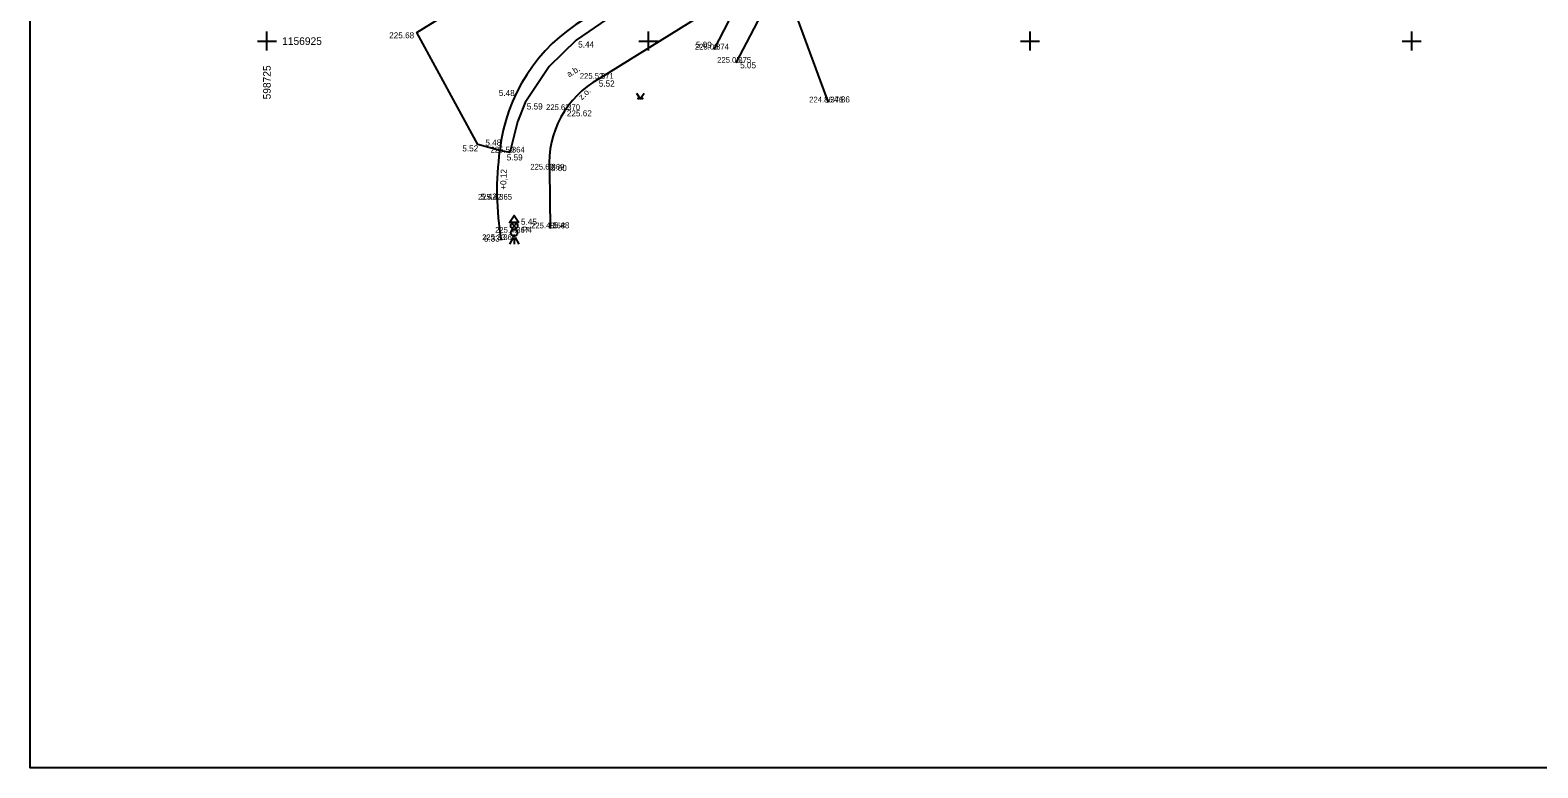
# Model space of a CAD drawing. Extents: x -598741 to -598592, y -1156973 to -1156763.
# Drawn here: x -598740.5 to -598641.7, y -1156972.6 to -1156924.3 of the extents above; entities that cross this region are included whole.
import ezdxf

# ---------------------------------------------------------------- set-up
doc = ezdxf.new("R2010")
doc.units = 0
for name, color, linetype in [('Vrstva 1', 7, 'Continuous'), ('Vrstva 10', 7, 'Continuous'), ('Vrstva 14', 7, 'Continuous'), ('Vrstva 2', 7, 'Continuous'), ('Vrstva 3', 7, 'Continuous'), ('Vrstva 44', 7, 'Continuous'), ('Vrstva 49', 7, 'Continuous'), ('Vrstva 50', 7, 'Continuous'), ('Vrstva 52', 7, 'Continuous'), ('Vrstva 58', 7, 'Continuous'), ('Vrstva 61', 7, 'Continuous'), ('Vrstva 62', 7, 'Continuous'), ('Vrstva 63', 7, 'Continuous'), ('Vrstva 7', 7, 'Continuous')]:
    doc.layers.add(name, color=color, linetype=linetype)

msp = doc.modelspace()

# ---------------------------------------------------------------- linework, layer by layer
at = {"layer": 'Vrstva 1'}
for p, q in [((-598695.71, -1156925.55), (-598695.71, -1156925.55)), ((-598694.25, -1156926.42), (-598694.25, -1156926.42)), ((-598703.25, -1156927.47), (-598703.25, -1156927.47)), ((-598705.46, -1156929.52), (-598705.46, -1156929.52)), ((-598688.22, -1156929.02), (-598688.22, -1156929.02)), ((-598709.09, -1156932.3), (-598709.09, -1156932.3)), ((-598706.49, -1156933.42), (-598706.49, -1156933.42)), ((-598709.92, -1156935.39), (-598709.92, -1156935.39)), ((-598708.8, -1156937.56), (-598708.8, -1156937.56)), ((-598706.44, -1156937.27), (-598706.44, -1156937.27)), ((-598709.65, -1156938.04), (-598709.65, -1156938.04))]:
    msp.add_line(p, q, dxfattribs=at)
at = {"layer": 'Vrstva 10'}
msp.add_lwpolyline([(-598621.74, -1156889.58), (-598642.9, -1156890.94), (-598644.87, -1156891.57), (-598666.18, -1156904.5), (-598682.28, -1156914.49), (-598689.54, -1156918.79), (-598690.41, -1156923.11), (-598688.22, -1156929.02)], dxfattribs=at)
at = {"layer": 'Vrstva 14'}
msp.add_lwpolyline([(-598700.79, -1156928.415), (-598700.54, -1156928.79), (-598700.29, -1156928.415)], dxfattribs=at)
for centre in [(-598700.665, -1156928.765), (-598700.415, -1156928.765)]:
    msp.add_circle(centre, 0.025, dxfattribs=at)
at = {"layer": 'Vrstva 44'}
for p, q in [((-598708.875, -1156937.86), (-598709.1, -1156938.31)), ((-598708.64, -1156936.95), (-598708.96, -1156937.27)), ((-598708.96, -1156936.95), (-598708.64, -1156937.27)), ((-598708.8, -1156937.86), (-598708.8, -1156938.31)), ((-598708.725, -1156937.86), (-598708.5, -1156938.31))]:
    msp.add_line(p, q, dxfattribs=at)
msp.add_lwpolyline([(-598708.496, -1156936.879), (-598709.098, -1156936.879), (-598708.799, -1156936.422)], close=True, dxfattribs=at)
for centre, radius in [((-598708.8, -1156937.11), 0.226), ((-598708.8, -1156937.56), 0.224)]:
    msp.add_circle(centre, radius, dxfattribs=at)
at = {"layer": 'Vrstva 61'}
msp.add_lwpolyline([(-598740.51, -1156762.629), (-598592.01, -1156762.63), (-598592.01, -1156972.63), (-598740.511, -1156972.63)], close=True, dxfattribs=at)
at = {"layer": 'Vrstva 62'}
for p, q in [((-598725.625, -1156925), (-598724.375, -1156925)), ((-598725, -1156925.625), (-598725, -1156924.375)), ((-598700.625, -1156925), (-598699.375, -1156925)), ((-598700, -1156925.625), (-598700, -1156924.375)), ((-598675.625, -1156925), (-598674.375, -1156925)), ((-598675, -1156925.625), (-598675, -1156924.375)), ((-598650.625, -1156925), (-598649.375, -1156925)), ((-598650, -1156925.625), (-598650, -1156924.375))]:
    msp.add_line(p, q, dxfattribs=at)
at = {"layer": 'Vrstva 63'}
msp.add_lwpolyline([(-598639.97, -1156884.56), (-598642.51, -1156885.7), (-598649.28, -1156889.83), (-598648.88, -1156890.41), (-598665.92, -1156901.18), (-598683.74, -1156912.35), (-598699.88, -1156922.5), (-598701.13, -1156922.47), (-598704.74, -1156924.93), (-598706.51, -1156926.67), (-598708.08, -1156929.03), (-598708.58, -1156930.282), (-598709.09, -1156932.3), (-598709.75, -1156932.17), (-598711.17, -1156931.77), (-598715.18, -1156924.43), (-598699.21, -1156914.53), (-598663.81, -1156892.35), (-598655, -1156886.83)], dxfattribs=at)
at = {"layer": 'Vrstva 7'}
msp.add_line((-598706.49, -1156933.42), (-598706.44, -1156937.27), dxfattribs=at)
for points in [[(-598694.25, -1156926.42), (-598690.23, -1156918.73), (-598682.6, -1156913.92), (-598664.75, -1156902.71), (-598647.68, -1156891.99), (-598647.45, -1156892.18), (-598645.76, -1156891.05)], [(-598703.25, -1156927.47), (-598693.87, -1156921.61), (-598693.78, -1156921.77), (-598695.71, -1156925.55)]]:
    msp.add_lwpolyline(points, dxfattribs=at)
for centre, radius, start, end in [((-598698.287, -1156933.456), 11.535, 120.72192, 173.59983), ((-598700.174, -1156933.002), 6.329, 119.07326, 183.78681), ((-598690.828, -1156934.783), 19.102, 172.13625, 189.81572)]:
    msp.add_arc(centre, radius, start, end, dxfattribs=at)

# ---------------------------------------------------------------- texts
at = {"layer": 'Vrstva 2'}
for s, p in [(' 374', (-598695.71, -1156925.55)), (' 375', (-598694.25, -1156926.42)), (' 371', (-598703.25, -1156927.47)), (' 376', (-598688.22, -1156929.02)), (' 370', (-598705.46, -1156929.52)), (' 364', (-598709.09, -1156932.3)), (' 369', (-598706.49, -1156933.42)), (' 365', (-598709.92, -1156935.39)), (' 368', (-598706.44, -1156937.27)), (' 366', (-598709.65, -1156938.04)), (' 367', (-598708.8, -1156937.56))]:
    msp.add_text(s, height=0.375, dxfattribs=at).set_placement(p)
at = {"layer": 'Vrstva 3'}
for s, p in [('225.09 ', (-598696.96, -1156925.55)), ('225.05 ', (-598695.5, -1156926.42)), ('225.52 ', (-598704.5, -1156927.47)), ('224.86 ', (-598689.47, -1156929.02)), ('225.62 ', (-598706.71, -1156929.52)), ('225.59 ', (-598710.34, -1156932.3)), ('225.60 ', (-598707.74, -1156933.42)), ('225.42 ', (-598711.17, -1156935.39)), ('225.48 ', (-598707.69, -1156937.27)), ('225.33 ', (-598710.9, -1156938.04)), ('225.45 ', (-598710.05, -1156937.56))]:
    msp.add_text(s, height=0.375, dxfattribs=at).set_placement(p)
at = {"layer": 'Vrstva 49'}
for s, rotation, p in [('a.b.', 30.58559, (-598705.208, -1156927.378)), ('z.o.', 43.38076, (-598704.365, -1156928.888))]:
    msp.add_text(s, height=0.4, rotation=rotation, dxfattribs=at).set_placement(p)
msp.add_text('P4', height=0.4, dxfattribs=at).set_placement((-598708.29, -1156937.56))
at = {"layer": 'Vrstva 50'}
msp.add_text('+0,12', height=0.4, rotation=88.47183, dxfattribs=at).set_placement((-598709.321, -1156934.744))
at = {"layer": 'Vrstva 52'}
msp.add_text('1156925', height=0.5, dxfattribs=at).set_placement((-598724, -1156925.25))
msp.add_text('598725', height=0.5, rotation=90, dxfattribs=at).set_placement((-598724.75, -1156928.82))
at = {"layer": 'Vrstva 58'}
for s, p in [('225.68', (-598716.988, -1156924.82)), ('5.44', (-598704.606, -1156925.42)), ('5.09', (-598696.896, -1156925.44)), ('5.05', (-598693.996, -1156926.78)), ('5.52', (-598703.256, -1156927.98)), ('5.48', (-598709.806, -1156928.6)), ('4.86', (-598687.846, -1156929.02)), ('5.59', (-598707.973, -1156929.48)), ('225.62', (-598705.348, -1156929.93)), ('5.52', (-598712.196, -1156932.23)), ('5.48', (-598710.686, -1156931.85)), ('5.59', (-598709.286, -1156932.82)), ('5.60', (-598706.393, -1156933.52)), ('5.42', (-598710.976, -1156935.39)), ('5.45', (-598708.356, -1156937.04)), ('5.48', (-598706.226, -1156937.27)), ('5.33', (-598710.782, -1156938.14))]:
    msp.add_text(s, height=0.4, dxfattribs=at).set_placement(p)

doc.saveas('drawing.dxf')
